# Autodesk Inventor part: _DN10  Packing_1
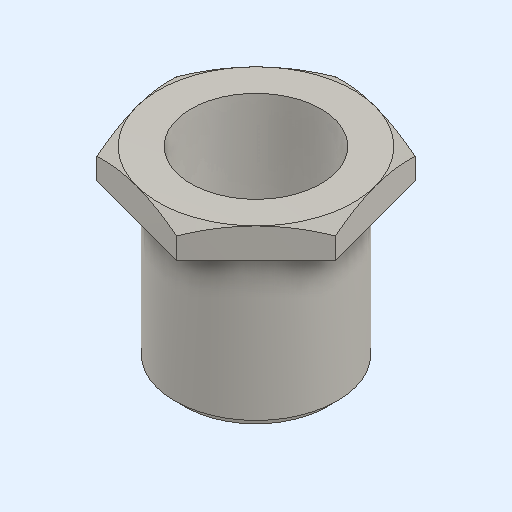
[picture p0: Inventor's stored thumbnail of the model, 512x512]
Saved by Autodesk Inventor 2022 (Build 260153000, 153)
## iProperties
Created: 2021-12
Part Number: _DN10  Packing_1
Material: Generico
Document SubType Name: Modeling
Designer: admin
Density: 1 g/cm^3
Appearance: Default
Author: admin
Revision Number: NONE
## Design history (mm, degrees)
feature "_DN10  Packing"
node "Solido1"
